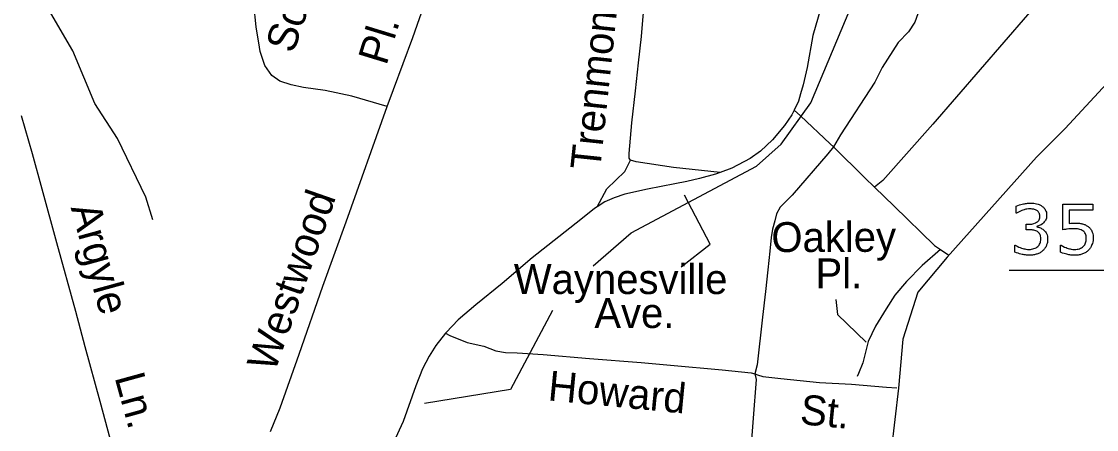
# Model space of a CAD drawing. Extents: x 925297 to 940193, y 663541 to 689899.
# Drawn here: x 929129 to 929667, y 688127 to 688331 of the extents above; entities that cross this region are included whole.
import ezdxf

# ---------------------------------------------------------------- set-up
doc = ezdxf.new("R2010")
doc.units = 0
doc.layers.add('Default', color=7, linetype='Continuous')

msp = doc.modelspace()

# ---------------------------------------------------------------- linework, layer by layer
at = {"layer": 'Default'}
for p, q in [((929588.97, 688216.9), (929593.1, 688214.09)), ((929623.37, 688206.64), (929711.16, 688206.64))]:
    msp.add_line(p, q, dxfattribs=at)
for points in [[(929414.97, 688208.79), (929433.96, 688225.32), (929496.81, 688258.69), (929509.21, 688269.84), (929523.98, 688290.52), (929543.64, 688337.07), (929570.32, 688422.17), (929595.25, 688470.11), (929641.53, 688544.1), (929648.24, 688563.88), (929649.28, 688581.85), (929658.96, 688617.52), (929685.35, 688661.41)], [(929954.77, 688606.42), (929947.23, 688598.43), (929915.57, 688562.81), (929863.58, 688508.48), (929842.43, 688488.75), (929834.66, 688480.99), (929804.98, 688446.9), (929760.27, 688396.54), (929716.11, 688347.67), (929651.43, 688277.65), (929637.01, 688263.22), (929592.29, 688213.18), (929577.66, 688195.5), (929570.1, 688171.94), (929567.9, 688147.4), (929562.37, 688100.19), (929560.82, 688077.15), (929557.05, 688048.99), (929557, 688048.94)], [(929766.17, 688488.37), (929749.41, 688469.03), (929736.3, 688453.99), (929719.22, 688434.65), (929705.47, 688418.91), (929694.03, 688405.79), (929678.59, 688387.54), (929662.33, 688368.55), (929647.17, 688351.55), (929632.64, 688334.68), (929585.17, 688279.86), (929560.06, 688251.62), (929555.97, 688248.14)], [(929569.95, 688480.77), (929556.84, 688463.98), (929551.28, 688451.83), (929544.4, 688426.93), (929539.03, 688415.4), (929536.07, 688407.26), (929534.72, 688396.19), (929534.36, 688384.82), (929535.15, 688363.97), (929533.06, 688350.8), (929530, 688341.4), (929525.01, 688324.27), (929522.12, 688308.28), (929520.15, 688299.54), (929518.92, 688295.07), (929517.81, 688291.34), (929515.7, 688286.89)], [(929194.44, 688231.89), (929190.85, 688243.23), (929176.68, 688272.55), (929165.3, 688290.18), (929154.23, 688316.6), (929142.17, 688337.44), (929136.32, 688375.28), (929141.14, 688420.33), (929133.86, 688440.2), (929131.57, 688454.71)], [(929247.8, 688318.49), (929246.08, 688328.54), (929244.96, 688339.91), (929246.01, 688348.65), (929247.65, 688358.24), (929250.45, 688365.96), (929254.48, 688373.57), (929262.46, 688390.52)], [(929311.84, 688288.64), (929314.89, 688297.18), (929324.67, 688323.22), (929342.29, 688373.99)], [(929433.62, 688261.73), (929433.04, 688262.72), (929433, 688263.64), (929432.94, 688265.12), (929434.42, 688280.53), (929436.14, 688296.47), (929437.61, 688310.56), (929439.12, 688323.75), (929440.07, 688333.96), (929440.99, 688343.63), (929442.45, 688358.53)], [(929578.53, 688337.4), (929576.09, 688330.94), (929572.96, 688326.18), (929567.76, 688320.74), (929559.79, 688308.2), (929556.05, 688300.92), (929538.95, 688274.47), (929535.33, 688268.45)], [(929311.84, 688288.64), (929294.14, 688293.76), (929280.72, 688296.68), (929269.87, 688298.23), (929263.69, 688299.48), (929258.07, 688301.41), (929254.01, 688304.2), (929250.48, 688309.19), (929248.18, 688316.28), (929247.8, 688318.49)], [(929253.37, 688125.67), (929258.1, 688137.62), (929267.63, 688164.5), (929279.49, 688198.49), (929291.22, 688230.87), (929311.84, 688288.64)], [(929185.46, 688076.32), (929184.09, 688080.79), (929175.51, 688112.79), (929167.96, 688140.71), (929160.42, 688168.06), (929155.83, 688185.87), (929146.33, 688220.36), (929138.93, 688247.28), (929134.13, 688264.91), (929128.59, 688283.93)], [(929515.7, 688286.89), (929514.56, 688284.5), (929510.82, 688279.08), (929504.76, 688271.96), (929498.76, 688266.23), (929493.71, 688262.57), (929484.39, 688257.79), (929478.6, 688255.56)], [(929515.7, 688286.89), (929518.91, 688284.02), (929533.79, 688269.97), (929535.33, 688268.45)], [(929535.33, 688268.45), (929532.49, 688264.84), (929514.73, 688244.21), (929508.71, 688238.16), (929506.9, 688234.9), (929505.92, 688231.39), (929504.87, 688227.18), (929504.18, 688223.03), (929503.42, 688216.12), (929502.45, 688206.68), (929501.39, 688195.96), (929499.85, 688182.99), (929497.09, 688159.05), (929496, 688154.52)], [(929535.33, 688268.45), (929551.05, 688252.95), (929555.97, 688248.14)], [(929416.92, 688238.41), (929421.85, 688247.3), (929430.82, 688256.04), (929433.62, 688261.73)], [(929478.6, 688255.56), (929455.16, 688258.15), (929436.5, 688260.86), (929433.62, 688261.73)], [(929478.6, 688255.56), (929476.3, 688254.67), (929468.24, 688252.54), (929461.96, 688251.12), (929455.89, 688249.91), (929442.14, 688247.27), (929430.83, 688244.66), (929425.44, 688242.85), (929420.77, 688240.9), (929416.92, 688238.41)], [(929555.97, 688248.14), (929565.74, 688238.6), (929585.99, 688218.92), (929588.97, 688216.9)], [(929459, 688208.33), (929473.58, 688219.59), (929460.67, 688244.18)], [(929416.92, 688238.41), (929415.59, 688237.55), (929408.82, 688232.02), (929384.42, 688212.79), (929369.39, 688199.93), (929356.26, 688189.15), (929347.29, 688181.64), (929341.29, 688175.36), (929340.95, 688174.92)], [(929627.05, 688235.09), (929626.88, 688235.09), (929626.88, 688238.6)], [(929650.25, 688226.77), (929650.25, 688239.64), (929665.29, 688239.64), (929665.29, 688236.71), (929653.48, 688236.71), (929653.48, 688230.06)], [(929633.46, 688226.83), (929631.94, 688226.83), (929631.94, 688229.6), (929633.12, 688229.6)], [(929637.18, 688228.55), (929637.18, 688228.32)], [(929626.17, 688215.69), (929626.17, 688219.2), (929626.42, 688219.2)], [(929649.17, 688215.57), (929649.17, 688219.11), (929649.41, 688219.11)], [(929588.97, 688216.9), (929579.84, 688208.99), (929572.02, 688200.82), (929566.06, 688194.02), (929561.81, 688187.22), (929556.36, 688178.54), (929552.79, 688170.88), (929550.07, 688160.17), (929547.86, 688154.72), (929547.18, 688153.19)], [(929536.6, 688191.94), (929537.44, 688184.33), (929551.8, 688170.53)], [(929394.66, 688186.33), (929373.49, 688146.79), (929330.45, 688139.73)], [(929340.95, 688174.92), (929336.11, 688168.77), (929332.79, 688163.51), (929329.5, 688157.08), (929326.13, 688148.56), (929319.77, 688130.74), (929314.9, 688120.18), (929311.09, 688114.57), (929306.01, 688109.43), (929299.17, 688105.29), (929294.06, 688103.67), (929288.22, 688102.67), (929277.51, 688103.14), (929260.9, 688105.64), (929255.44, 688105.95)], [(929340.95, 688174.92), (929343.1, 688173.78), (929351.79, 688170.26), (929360.21, 688168.44), (929366.28, 688166.12), (929371.01, 688165.34), (929376.9, 688165.05), (929389.9, 688164.27), (929413.21, 688162.27), (929438.96, 688160.2), (929453.75, 688159.02), (929479.62, 688156.62), (929494.11, 688155.1), (929496, 688154.52)], [(929496, 688154.52), (929496.7, 688151.76), (929493.69, 688112.91)], [(929496, 688154.52), (929497.35, 688154.11), (929500.05, 688153.29), (929508.96, 688152.27), (929528.3, 688150.25), (929544.47, 688149.4), (929561.94, 688147.97), (929567.07, 688147.58)]]:
    msp.add_lwpolyline(points, dxfattribs=at)
for points in [[(929626.88, 688238.6), (929628.07, 688239.19), (929630.07, 688239.68), (929632.06, 688240.18), (929633.92, 688240.18), (929635.76, 688240.18), (929637.15, 688239.84), (929638.55, 688239.5), (929639.67, 688238.76), (929640.88, 688237.96), (929641.5, 688236.82), (929642.13, 688235.67), (929642.13, 688234.14), (929642.13, 688232.06), (929640.65, 688230.51), (929639.18, 688228.95), (929637.18, 688228.55)], [(929633.12, 688229.6), (929635.67, 688229.6), (929637.2, 688230.67), (929638.72, 688231.74), (929638.72, 688233.79), (929638.72, 688234.7), (929638.33, 688235.38), (929637.94, 688236.07), (929637.25, 688236.5), (929636.53, 688236.94), (929635.71, 688237.11), (929634.88, 688237.28), (929633.84, 688237.28), (929632.24, 688237.28), (929630.45, 688236.71), (929628.65, 688236.14), (929627.05, 688235.09)], [(929653.48, 688230.06), (929654.2, 688230.13), (929654.96, 688230.16), (929655.71, 688230.2), (929656.27, 688230.2), (929658.3, 688230.2), (929659.83, 688229.85), (929661.36, 688229.51), (929662.63, 688228.63), (929663.98, 688227.71), (929664.72, 688226.25), (929665.46, 688224.78), (929665.46, 688222.58)], [(929640.79, 688226.69), (929641.6, 688225.96), (929642.12, 688224.87), (929642.64, 688223.78), (929642.64, 688222.05), (929642.64, 688220.33), (929642.01, 688218.9), (929641.39, 688217.48), (929640.27, 688216.42), (929639.01, 688215.24), (929637.31, 688214.68), (929635.6, 688214.11), (929633.57, 688214.11), (929631.49, 688214.11), (929629.47, 688214.61), (929627.46, 688215.1), (929626.17, 688215.69)], [(929626.42, 688219.2), (929627.85, 688218.26), (929629.78, 688217.63), (929631.71, 688217.01), (929633.51, 688217.01), (929634.57, 688217.01), (929635.76, 688217.37), (929636.96, 688217.72), (929637.7, 688218.41), (929638.47, 688219.15), (929638.85, 688220.04), (929639.23, 688220.94), (929639.23, 688222.3), (929639.23, 688223.65), (929638.8, 688224.53), (929638.37, 688225.41), (929637.61, 688225.92), (929636.86, 688226.44), (929635.78, 688226.63), (929634.7, 688226.83), (929633.46, 688226.83)], [(929637.18, 688228.32), (929637.99, 688228.18), (929639.03, 688227.75), (929640.07, 688227.32), (929640.79, 688226.69)], [(929649.41, 688219.11), (929650.78, 688218.24), (929652.63, 688217.63), (929654.48, 688217.01), (929656.26, 688217.01), (929657.45, 688217.01), (929658.56, 688217.35), (929659.68, 688217.69), (929660.55, 688218.53), (929661.29, 688219.25), (929661.67, 688220.26), (929662.05, 688221.27), (929662.05, 688222.6), (929662.05, 688223.9), (929661.6, 688224.79), (929661.16, 688225.68), (929660.37, 688226.22), (929659.5, 688226.86), (929658.25, 688227.12), (929657, 688227.38), (929655.45, 688227.38), (929653.98, 688227.38), (929652.61, 688227.18), (929651.24, 688226.97), (929650.25, 688226.77)], [(929665.46, 688222.58), (929665.46, 688220.84), (929664.82, 688219.24), (929664.18, 688217.64), (929663.07, 688216.55), (929661.86, 688215.37), (929660.19, 688214.74), (929658.52, 688214.11), (929656.32, 688214.11), (929654.27, 688214.11), (929652.38, 688214.54), (929650.48, 688214.97), (929649.17, 688215.57)]]:
    msp.add_open_spline(points, degree=3, dxfattribs=at)

# ---------------------------------------------------------------- texts
for s, rotation, p in [('Southwick', 71.4369, (929264.77, 688314.76)), ('Trenmont', 83.9555, (929418.43, 688256.33)), ('Pl.', 72.9588, (929311.34, 688308.81)), ('Westwood', 70.759, (929255.42, 688154.92)), ('Argyle', 285.4048, (929153.17, 688237.94)), ('Oakley', 0.1496, (929504.29, 688215.65)), ('Pl.', 359.9004, (929526.36, 688197.48)), ('Waynesville', 359.9846, (929375.25, 688194.62)), ('Ave.', 0.1082, (929415.57, 688177.53)), ('Ln.', 285.4048, (929175.14, 688152.87)), ('Howard', 354.4608, (929391.94, 688141.33)), ('St.', 354.3436, (929518.22, 688129.43))]:
    msp.add_text(s, height=15, rotation=rotation, dxfattribs=at).set_placement(p)

doc.saveas('drawing.dxf')
